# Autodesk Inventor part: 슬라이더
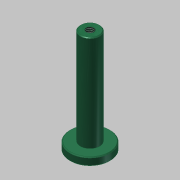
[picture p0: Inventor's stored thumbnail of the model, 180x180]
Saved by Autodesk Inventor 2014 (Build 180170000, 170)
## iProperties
Created: 2016-02
Part Number: 슬라이더
Material: 스테인리스강
Document SubType Name: Modeling
Designer: mduedu
Density: 8.08 g/cm^3
Appearance: Smooth - Dark Sea Green
Mass: 72.5507 g
Surface Area: 37.669 cm^2
Volume: 8.97904 cm^3
Author: mduedu
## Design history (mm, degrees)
sketch "스케치1"
  geometry: C1 r 12.5 at (0, 0); 1 further point
  constraints: 1 centre point, 1 coincident
  dimensions: "d0" = 25 diameter of C1
extrude "돌출1" new body sketch "스케치1" distance "d1" = 5; taper "d2" = 0 deg
sketch "스케치2"
  geometry: C1 r 6 at (0, 0); 1 further point
  constraints: 1 centre point, 1 coincident
  dimensions: "d3" = 12 diameter of C1
extrude "돌출2" join sketch "스케치2" distance "d4" = 60; taper "d5" = 0 deg
chamfer "모따기1" distance "d6" = 0.5; stored, may be unused: second distance "d7" = 2, angle "d8" = 45 deg
hole "구멍1" diameter "d11" = 4.917; stored, may be unused: countersink angle "d15" = 90 deg, drill point angle "d17" = 118 deg; dims "d9" = 10, "d10" = 10, "d12" = 10, "d13" = 4, "d14" = 2, "d16" = 12
chamfer "모따기2" distance "d18" = 0.5; stored, may be unused: second distance "d19" = 2, angle "d20" = 45 deg
sketch "스케치3"
  geometry: L1 (-12.5, 4.5)-(-12, 5) reference; L2 (-12, 5)-(-6, 5) reference; L3 (-6, 5)-(-6, 64.5) reference; L4 (-6, 64.5)-(-5.5, 65) reference; L5 (-5.5, 65)-(-2.458, 65) reference; L6 (-2.458, 65)-(-2.458, 53) reference; L7 (-2.458, 53)-(0, 51.523) reference; L8 (0, 51.523)-(2.458, 53) reference; L9 (2.458, 53)-(2.458, 65) reference; L10 (2.458, 65)-(5.5, 65) reference; L11 (5.5, 65)-(6, 64.5) reference; L12 (6, 64.5)-(6, 5) reference; L13 (6, 5)-(12, 5) reference; L14 (12, 5)-(12.5, 4.5) reference; L15 (12.5, 4.5)-(12.5, 0.5) reference; L16 (12.5, 0.5)-(12, 0) reference; L17 (12, 0)-(-12, 0) reference; L18 (-12, 0)-(-12.5, 0.5) reference; L19 (-12.5, 0.5)-(-12.5, 4.5) reference; 1 further point
  node "절단 모서리 투영1"
node "솔리드1"
